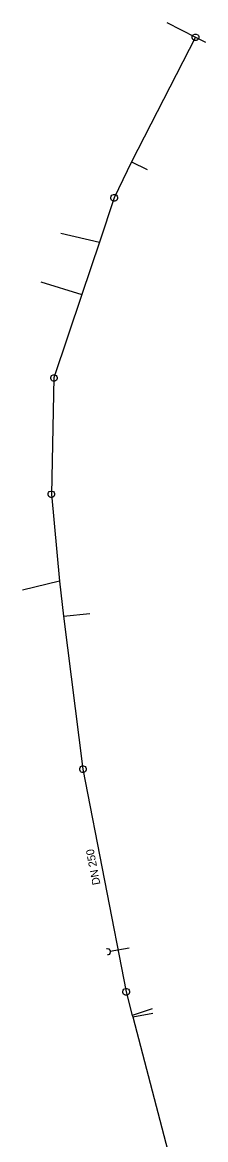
# Model space of a CAD drawing. Extents: x -717256 to -716843, y -1145423 to -1142840.
# Drawn here: x -717064.7 to -717036.1, y -1143014.1 to -1142839.6 of the extents above; entities that cross this region are included whole.
import ezdxf

# ---------------------------------------------------------------- set-up
doc = ezdxf.new("R2010")
doc.units = 0
for name, color, linetype in [('Vrstva 30', 7, 'Continuous'), ('Vrstva 31', 7, 'Continuous'), ('Vrstva 9', 7, 'Continuous')]:
    doc.layers.add(name, color=color, linetype=linetype)

msp = doc.modelspace()

# ---------------------------------------------------------------- linework, layer by layer
at = {"layer": 'Vrstva 30'}
for p, q in [((-717038.207, -1142841.849), (-717038.157, -1142841.699)), ((-717038.207, -1142842.049), (-717038.207, -1142841.849)), ((-717038.157, -1142841.699), (-717038.057, -1142841.549)), ((-717038.057, -1142841.549), (-717037.807, -1142841.449)), ((-717037.807, -1142841.449), (-717037.607, -1142841.449)), ((-717037.607, -1142841.449), (-717037.357, -1142841.549)), ((-717037.357, -1142841.549), (-717037.257, -1142841.699)), ((-717037.257, -1142841.699), (-717037.207, -1142841.849)), ((-717037.207, -1142841.849), (-717037.207, -1142842.049)), ((-717037.707, -1142841.949), (-717047.71, -1142861.423)), ((-717038.107, -1142842.299), (-717038.207, -1142842.049)), ((-717037.957, -1142842.399), (-717038.107, -1142842.299)), ((-717037.807, -1142842.449), (-717037.957, -1142842.399)), ((-717037.607, -1142842.449), (-717037.807, -1142842.449)), ((-717037.457, -1142842.399), (-717037.607, -1142842.449)), ((-717037.307, -1142842.299), (-717037.457, -1142842.399)), ((-717037.207, -1142842.049), (-717037.307, -1142842.299)), ((-717047.71, -1142861.423), (-717050.395, -1142867.026)), ((-717050.395, -1142867.026), (-717052.702, -1142873.921)), ((-717050.895, -1142866.926), (-717050.845, -1142866.776)), ((-717050.895, -1142867.126), (-717050.895, -1142866.926)), ((-717050.795, -1142867.376), (-717050.895, -1142867.126)), ((-717050.845, -1142866.776), (-717050.745, -1142866.626)), ((-717050.645, -1142867.476), (-717050.795, -1142867.376)), ((-717050.745, -1142866.626), (-717050.495, -1142866.526)), ((-717050.495, -1142867.526), (-717050.645, -1142867.476)), ((-717050.495, -1142866.526), (-717050.295, -1142866.526)), ((-717050.295, -1142867.526), (-717050.495, -1142867.526)), ((-717050.295, -1142866.526), (-717050.045, -1142866.626)), ((-717050.145, -1142867.476), (-717050.295, -1142867.526)), ((-717049.995, -1142867.376), (-717050.145, -1142867.476)), ((-717050.045, -1142866.626), (-717049.945, -1142866.776)), ((-717049.895, -1142867.126), (-717049.995, -1142867.376)), ((-717049.945, -1142866.776), (-717049.895, -1142866.926)), ((-717049.895, -1142866.926), (-717049.895, -1142867.126)), ((-717052.702, -1142873.921), (-717055.443, -1142882.114)), ((-717055.443, -1142882.114), (-717059.805, -1142895.147)), ((-717060.305, -1142895.047), (-717060.255, -1142894.897)), ((-717060.305, -1142895.247), (-717060.305, -1142895.047)), ((-717060.205, -1142895.497), (-717060.305, -1142895.247)), ((-717060.255, -1142894.897), (-717060.155, -1142894.747)), ((-717060.055, -1142895.597), (-717060.205, -1142895.497)), ((-717059.805, -1142895.147), (-717060.198, -1142913.293)), ((-717060.155, -1142894.747), (-717059.905, -1142894.647)), ((-717059.905, -1142895.647), (-717060.055, -1142895.597)), ((-717059.905, -1142894.647), (-717059.705, -1142894.647)), ((-717059.705, -1142895.647), (-717059.905, -1142895.647)), ((-717059.705, -1142894.647), (-717059.455, -1142894.747)), ((-717059.555, -1142895.597), (-717059.705, -1142895.647)), ((-717059.405, -1142895.497), (-717059.555, -1142895.597)), ((-717059.455, -1142894.747), (-717059.355, -1142894.897)), ((-717059.305, -1142895.247), (-717059.405, -1142895.497)), ((-717059.355, -1142894.897), (-717059.305, -1142895.047)), ((-717059.305, -1142895.047), (-717059.305, -1142895.247)), ((-717060.698, -1142913.193), (-717060.648, -1142913.043)), ((-717060.698, -1142913.393), (-717060.698, -1142913.193)), ((-717060.598, -1142913.643), (-717060.698, -1142913.393)), ((-717060.648, -1142913.043), (-717060.548, -1142912.893)), ((-717060.548, -1142912.893), (-717060.298, -1142912.793)), ((-717060.298, -1142912.793), (-717060.098, -1142912.793)), ((-717060.198, -1142913.293), (-717058.928, -1142926.861)), ((-717060.098, -1142912.793), (-717059.848, -1142912.893)), ((-717059.848, -1142912.893), (-717059.748, -1142913.043)), ((-717059.698, -1142913.393), (-717059.798, -1142913.643)), ((-717059.748, -1142913.043), (-717059.698, -1142913.193)), ((-717059.698, -1142913.193), (-717059.698, -1142913.393)), ((-717060.448, -1142913.743), (-717060.598, -1142913.643)), ((-717060.298, -1142913.793), (-717060.448, -1142913.743)), ((-717060.098, -1142913.793), (-717060.298, -1142913.793)), ((-717059.948, -1142913.743), (-717060.098, -1142913.793)), ((-717059.798, -1142913.643), (-717059.948, -1142913.743)), ((-717058.928, -1142926.861), (-717058.296, -1142932.328)), ((-717058.296, -1142932.328), (-717055.275, -1142956.223)), ((-717055.775, -1142956.123), (-717055.725, -1142955.973)), ((-717055.775, -1142956.323), (-717055.775, -1142956.123)), ((-717055.675, -1142956.573), (-717055.775, -1142956.323)), ((-717055.725, -1142955.973), (-717055.625, -1142955.823)), ((-717055.525, -1142956.673), (-717055.675, -1142956.573)), ((-717055.625, -1142955.823), (-717055.375, -1142955.723)), ((-717055.375, -1142956.723), (-717055.525, -1142956.673)), ((-717055.375, -1142955.723), (-717055.175, -1142955.723)), ((-717055.175, -1142956.723), (-717055.375, -1142956.723)), ((-717055.275, -1142956.223), (-717048.528, -1142990.983)), ((-717055.175, -1142955.723), (-717054.925, -1142955.823)), ((-717055.025, -1142956.673), (-717055.175, -1142956.723)), ((-717054.875, -1142956.573), (-717055.025, -1142956.673)), ((-717054.925, -1142955.823), (-717054.825, -1142955.973)), ((-717054.775, -1142956.323), (-717054.875, -1142956.573)), ((-717054.825, -1142955.973), (-717054.775, -1142956.123)), ((-717054.775, -1142956.123), (-717054.775, -1142956.323)), ((-717049.028, -1142990.883), (-717048.978, -1142990.733)), ((-717049.028, -1142991.083), (-717049.028, -1142990.883)), ((-717048.928, -1142991.333), (-717049.028, -1142991.083)), ((-717048.978, -1142990.733), (-717048.878, -1142990.583)), ((-717048.778, -1142991.433), (-717048.928, -1142991.333)), ((-717048.878, -1142990.583), (-717048.628, -1142990.483)), ((-717048.628, -1142991.483), (-717048.778, -1142991.433)), ((-717048.628, -1142990.483), (-717048.428, -1142990.483)), ((-717048.428, -1142991.483), (-717048.628, -1142991.483)), ((-717048.528, -1142990.983), (-717047.566, -1142994.652)), ((-717048.428, -1142990.483), (-717048.178, -1142990.583)), ((-717048.278, -1142991.433), (-717048.428, -1142991.483)), ((-717048.128, -1142991.333), (-717048.278, -1142991.433)), ((-717048.178, -1142990.583), (-717048.078, -1142990.733)), ((-717048.028, -1142991.083), (-717048.128, -1142991.333)), ((-717048.078, -1142990.733), (-717048.028, -1142990.883)), ((-717048.028, -1142990.883), (-717048.028, -1142991.083)), ((-717047.566, -1142994.652), (-717047.501, -1142994.899)), ((-717047.501, -1142994.899), (-717038.15, -1143030.578))]:
    msp.add_line(p, q, dxfattribs=at)
at = {"layer": 'Vrstva 31'}
for p, q in [((-717042.172, -1142839.625), (-717037.707, -1142841.949)), ((-717037.707, -1142841.949), (-717036.126, -1142842.708)), ((-717047.71, -1142861.423), (-717045.242, -1142862.608)), ((-717058.728, -1142872.55), (-717052.702, -1142873.921)), ((-717061.827, -1142880.156), (-717055.443, -1142882.114)), ((-717058.928, -1142926.861), (-717064.727, -1142928.278)), ((-717058.296, -1142932.328), (-717054.182, -1142931.938)), ((-717044.464, -1142993.633), (-717047.566, -1142994.652)), ((-717047.501, -1142994.899), (-717044.384, -1142994.298))]:
    msp.add_line(p, q, dxfattribs=at)
at = {"layer": 'Vrstva 9'}
for p, q in [((-717051.6, -1142984.239), (-717051.502, -1142984.222)), ((-717051.502, -1142984.222), (-717051.238, -1142984.277)), ((-717051.238, -1142984.277), (-717051.114, -1142984.408)), ((-717051.114, -1142984.408), (-717051.039, -1142984.547)), ((-717051.005, -1142984.744), (-717051.06, -1142985.007)), ((-717051.039, -1142984.547), (-717051.005, -1142984.744)), ((-717051.022, -1142984.645), (-717048.067, -1142984.13)), ((-717051.33, -1142985.207), (-717051.428, -1142985.224)), ((-717051.191, -1142985.132), (-717051.33, -1142985.207)), ((-717051.06, -1142985.007), (-717051.191, -1142985.132))]:
    msp.add_line(p, q, dxfattribs=at)

# ---------------------------------------------------------------- texts
at = {"layer": 'Vrstva 30'}
msp.add_text('DN 250', height=1.25, rotation=100.8, dxfattribs=at).set_placement((-717052.538, -1142974.173))

doc.saveas('drawing.dxf')
